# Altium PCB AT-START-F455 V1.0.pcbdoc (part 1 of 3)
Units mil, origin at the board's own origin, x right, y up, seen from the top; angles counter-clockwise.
Board outline 10945.53 x 3554 mil, 2 copper layers (Top Layer, Bottom Layer); 149 components, 197 nets, 740 pads, 768 vias.
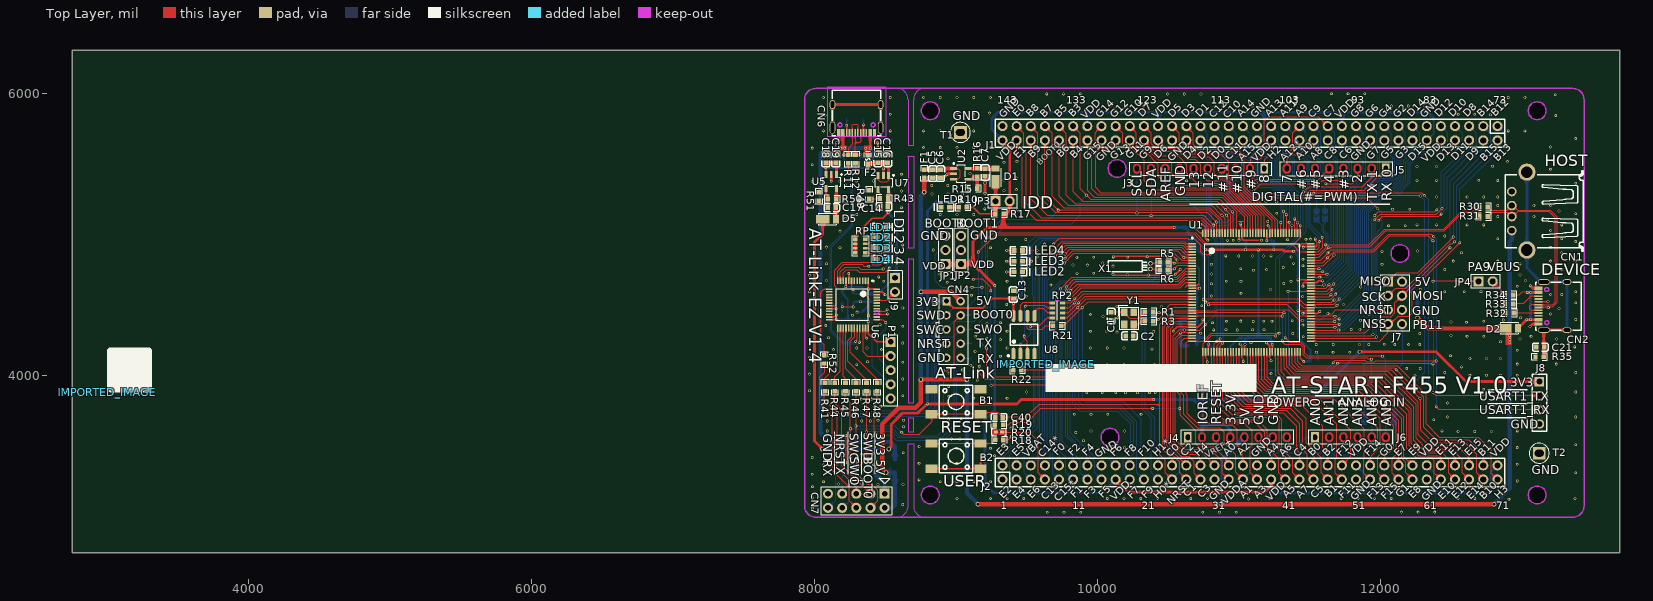
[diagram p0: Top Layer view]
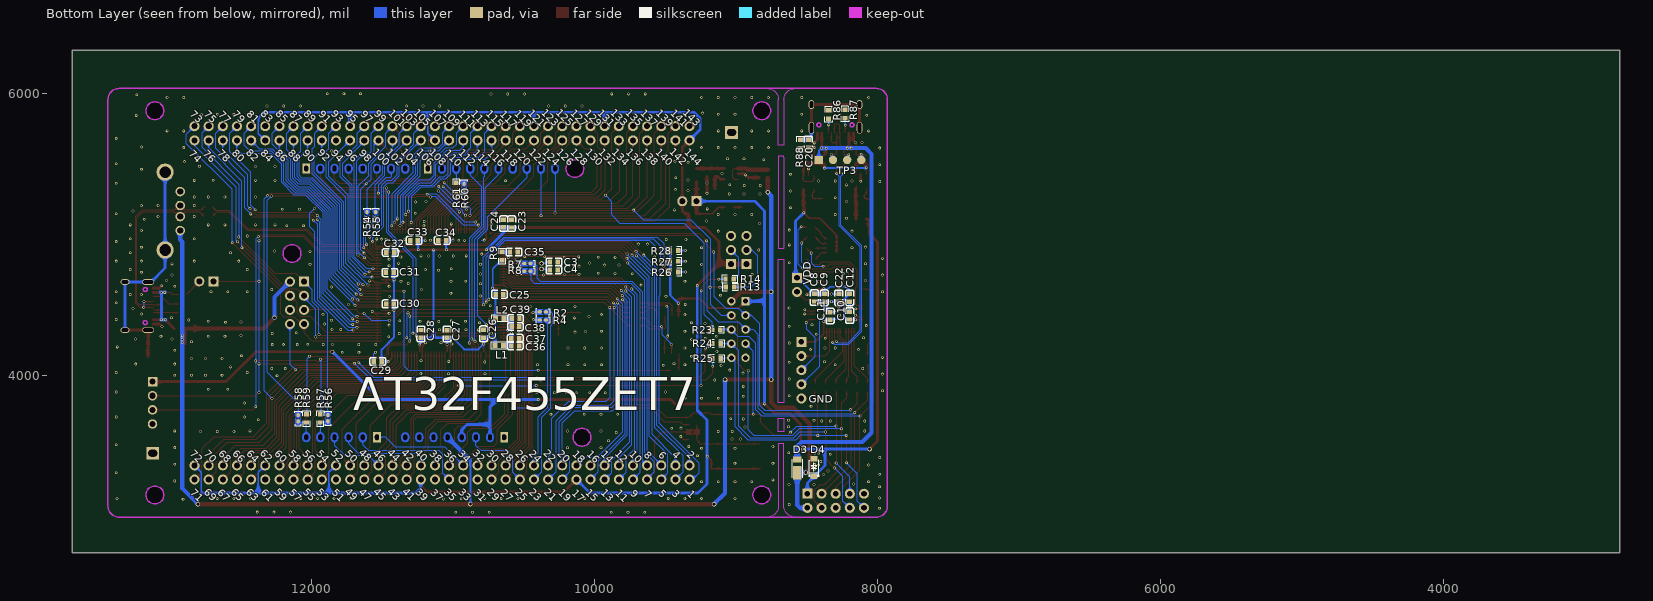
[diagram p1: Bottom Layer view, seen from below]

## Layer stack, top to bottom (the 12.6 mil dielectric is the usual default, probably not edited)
Top Layer: signal copper (thickness not stored)
Dielectric: dielectric 12.6, FR-4, Dk 4.8
Bottom Layer: signal copper (thickness not stored)

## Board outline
13695.53,2750 2750,2750 2750,6304 13695.53,6304
cut-out: 12202.8,4865.97 ccw(c12139.81,4865.43) 12076.82,4865.97 ccw(c12139.81,4866.51)
cut-out: 10202.8,5465.96 ccw(c10139.81,5465.42) 10076.82,5465.96 ccw(c10139.81,5466.5)
cut-out: 10152.8,3565.97 ccw(c10089.81,3565.43) 10026.82,3565.97 ccw(c10089.81,3566.51)
cut-out: 8881.38,5874.63 ccw(c8818.39,5874.09) 8755.4,5874.63 ccw(c8818.39,5875.17)
cut-out: 8881.38,3158.09 ccw(c8818.39,3157.55) 8755.4,3158.09 ccw(c8818.39,3158.63)
cut-out: 13172.72,3158.09 ccw(c13109.73,3157.55) 13046.74,3158.09 ccw(c13109.73,3158.63)
cut-out: 13172.72,5874.63 ccw(c13109.73,5874.09) 13046.74,5874.63 ccw(c13109.73,5875.17)

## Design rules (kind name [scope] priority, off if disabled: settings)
BoardOutlineClearance copperThickness1oz [All] p0: genericclearance=10 ignorepadtopadclearanceinfootprint=FALSE except(0: Arc-SplitContinuation Track-SplitContinuation SMDPad-SplitContinuation THPad-SplitContinuation Via-SplitContinuation Fill-SplitContinuation Poly-SplitContinuation Region-SplitContinuation Text-SplitContinuation; 6: SMDPad-CutoutEdge THPad-CutoutEdge Via-CutoutEdge Fill-CutoutEdge Region-CutoutEdge; 11.8: Track-OutlineEdge SMDPad-OutlineEdge THPad-OutlineEdge Via-OutlineEdge Fill-OutlineEdge Region-OutlineEdge Poly-OutlineEdge Text-OutlineEdge Track-CutoutEdge)
Clearance copperThickness1oz [(InNet('GND') OR InNet('PB11') OR InNet('PB9') OR InNet('PB8') OR InNet('PD4') OR InNet('PD1') OR InNet('PA1') OR InNet('PC1') OR InNet('PE15') OR InNet('PB10') OR InNet('PG6') OR InNet('PD10') OR InNet('PD9') OR InNet('PD8') OR InNet('PG15') OR InNet('PA2') OR InNet('PC0') OR InNet('PC2') OR InNet('NRST') OR InNet('PA15') OR InNet('PA13/SWDIO') OR InNet('PA14/SWCLK') OR InNet('VDD') OR InNet('PA3') OR InNet('PB2/BOOT1') OR InNet('3V3') OR InNet('PA0') OR InNet('PA5') OR InNet('PA6') OR InNet('PA7') OR InNet('PD0') OR InNet('PA9') OR InNet('PA10') OR InNet('PG14') OR InNet('PG13') OR InNet('PG11') OR InNet('PB5') OR InNet('PB6') OR InNet('PD2') OR InNet('PC12') OR InNet('PC11') OR InNet('PC10') OR InNet('VBAT') OR InNet('VDDA') OR InNet('VREF+') OR InNet('PD11') OR InNet('PD12') OR InNet('PD13') OR InNet('PD14') OR InNet('PD15') OR InNet('PG2') OR InNet('PG3') OR InNet('PG4') OR InNet('PG5') OR InNet('PG7') OR InNet('PG8') OR InNet('PC6') OR InNet('PC7') OR InNet('PC8') OR InNet('PC9') OR InNet('PA8') OR InNet('PH2') OR InNet('PH0/HEXT_IN') OR InNet('PH1/HEXT_OUT') OR InNet('PF10') OR InNet('PF9') OR InNet('PF8') OR InNet('PF7') OR InNet('PF6') OR InNet('PF5') OR InNet('PF4') OR InNet('PF3') OR InNet('PF2') OR InNet('PF1') OR InNet('PF0') OR InNet('PC13') OR InNet('PE6') OR InNet('PE5') OR InNet('PE4') OR InNet('PE3') OR InNet('PE2') OR InNet('PC15/LEXT_OUT') OR InNet('PC14/LEXT_IN') OR InNet('SWO') OR InNet('ATLK_RX') OR InNet('LD4') OR InNet('VCC') OR InNet('M-NRST') OR InNet('ATLK_TX') OR InNet('ATLINK_5V') OR InNet('PH3') OR InNet('PB3') OR InNet('QSPI1_IO2') OR InNet('QSPI1_IO1') OR InNet('PB4') OR InNet('PH1_E') OR InNet('PH0_E') OR InNet('PC15_E') OR InNet('PC14_E') OR InNet('PA11_E') OR InNet('PA12_E') OR InNet('PB0') OR InNet('PA4') OR InNet('PE10') OR InNet('PC4') OR InNet('VCC3.5V') OR InNet('PG0') OR InNet('PE7') OR InNet('PE8') OR InNet('PG1') OR InNet('LD3') OR InNet('LD2') OR InNet('LD1') OR InNet('PD3') OR InNet('PG9') OR InNet('PD6') OR InNet('M-SWDIO') OR InNet('M-ATLK_RX') OR InNet('M-ATLK_TX') OR InNet('PE1') OR InNet('PC3') OR InNet('PD7') OR InNet('PG10') OR InNet('PG12') OR InNet('M-SWCLK') OR InNet('PC5') OR InNet('PE12') OR InNet('PE11') OR InNet('PF15') OR InNet('PF14') OR InNet('PE13') OR InNet('PE14') OR InNet('PE9') OR InNet('PF12') OR InNet('PF13') OR InNet('PB1') OR InNet('PB7') OR InNet('PD5') OR InNet('PE0') OR InNet('QSPI1_SCK') OR InNet('PF11') OR InNet('QSPI1_IO0') OR InNet('QSPI1_IO3') OR InNet('$2N452') OR InNet('$2N453') OR InNet('$2N511') OR InNet('$2N512') OR InNet('$2N702') OR InNet('$2N701') OR InNet('$3N82') OR InNet('$3N81') OR InNet('$3N119') OR InNet('$3N184') OR InNet('$3N504') OR InNet('$3N505') OR InNet('$3N506') OR InNet('$4N269') OR InNet('$4N270') OR InNet('$4N339') OR InNet('$3N58') OR InNet('EGND1') OR InNet('OTGFS1_D-') OR InNet('OTGFS1_D+') OR InNet('PB12') OR InNet('PB13') OR InNet('PB14') OR InNet('PB15') OR InNet('PH4') OR InNet('QSPI1_CS') OR InNet('$3N17593') OR InNet('ATLK_SWCLK') OR InNet('$6N17598') OR InNet('ATLK_SWDIO') OR InNet('ATLK_BOOT0') OR InNet('ATLK_NRST') OR InNet('$6N17675') OR InNet('ATLK_SWO') OR InNet('PA11') OR InNet('PA12') OR InNet('$6N16959') OR InNet('EGND') OR InNet('$3N17443') OR InNet('$3N17484') OR InNet('CC2') OR InNet('USBP') OR InNet('USBM') OR InNet('CC1') OR InNet('M-BOOT0') OR InNet('$6N792') OR InNet('$6N793') OR InNet('$6N794') OR InNet('$6N795') OR InNet('M-USB_DP') OR InNet('M-USB_DM') OR InNet('5V') OR InNet('BOOT0') OR InNet('VBUS'))] p1: gap=7 ignorepadtopadclearanceinfootprint=FALSE except(6: Track-Track Track-SMDPad SMDPad-SMDPad Track-THPad SMDPad-THPad THPad-THPad Track-Via SMDPad-Via THPad-Via Via-Via Track-Fill SMDPad-Fill THPad-Fill Via-Fill Fill-Fill SMDPad-Region THPad-Region Via-Region Fill-Region Region-Region Track-Poly SMDPad-Poly THPad-Poly Via-Poly Fill-Poly Poly-Poly Track-Text SMDPad-Text THPad-Text Via-Text Fill-Text Region-Text Poly-Text Text-Text; 6.9: Track-Hole SMDPad-Hole THPad-Hole Via-Hole Fill-Hole Region-Hole Poly-Hole Text-Hole Sheet-Hole; 11.8: Track-Region Region-Poly Track-Sheet SMDPad-Sheet THPad-Sheet Via-Sheet Fill-Sheet Region-Sheet Poly-Sheet Text-Sheet)
DiffPairsRouting differentialPair [All] p1: maxuncoupledlength=10 minlimit=5.9843 maxlimit=5.9843 mostfreqgap=5.9843 toplayer_minwidth=5 toplayer_prefwidth=10 toplayer_maxwidth=100 bottomlayer_minwidth=5 bottomlayer_prefwidth=10 bottomlayer_maxwidth=100
PasteMaskExpansion pasteMaskExpansion [All] p1: expansion=0
PlaneConnect innerPlane [All] p1: planeconnectstyle=Relief reliefexpansion=20 reliefentries=4 reliefconductorwidth=10 reliefairgap=10
PolygonConnect copperRegion [All] p1: connectstyle=Relief reliefentries=4 reliefconductorwidth=10 polygonreliefangle="90 Angle" airgapwidth=10
RoutingVias viaSize [All] p1: viastyle="Through Hole" holewidth=11.811 minholewidth=11.811 maxholewidth=19.685 width=19.685 minwidth=19.685 maxwidth=31.496
SolderMaskExpansion solderMaskExpansion [All] p1: useseparateexpansions=TRUE expansion=2.0079 expansionbottom=2.0079
Width copperThickness1oz [All] p1: maxlimit=100 minlimit=6 preferedwidth=6

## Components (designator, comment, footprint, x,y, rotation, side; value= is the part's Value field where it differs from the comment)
B1 "贴片按键6*6*5 黑色" SW-SMD_4P-L6.0-W6.0-P4.50-LS9.0 9001.26,3816.97 r180 top
B2 "贴片按键6*6*5 红色" SW-SMD_4P-L6.0-W6.0-P4.50-LS9.0 9001.26,3432.97 r180 top
C1 "CL10C150JB8NNNC" C0603 10097.57,4422.61 r90 top
C2 "CL10C150JB8NNNC" C0603 10227.57,4282.61 r0 top
C3 "CL10C180JB8NNNC" C0603 10288.61,4805.53 r0 bottom
C4 "CL10C180JB8NNNC" C0603 10288.61,4749.97 r0 bottom
C5 "CL10A106KP8NNNC" C0603 8836.21,5429.61 r270 top
C6 "CC0603KRX7R9BB104" C0603 8891.21,5429.61 r270 top
C7 "CL10A106KP8NNNC" C0603 9206.21,5437.97 r270 top
C8 "CL10A475KO8NNNC" C0603 8446.37,4553.41 r90 bottom
C9 "CC0603KRX7R9BB104" C0603 8376.37,4552.61 r90 bottom
C10 "CC0603KRX7R9BB104" C0603 8196.77,4426.21 r270 bottom
C11 "CC0603KRX7R9BB104" C0603 8335.17,4423.41 r270 bottom
C12 "CC0603KRX7R9BB104" C0603 8196.37,4552.21 r90 bottom
C13 "CC0603KRX7R9BB104" C0603 9406.18,4574.85 r90 top
C14 "CL10A106KP8NNNC" C0603 8491.81,5197.16 r0 top
C15 "CL10A106KP8NNNC" C0603 8448.56,5534.05 r270 top
C16 "CC0603KRX7R9BB104" C0603 8517.56,5534.05 r270 top
C17 "CL10A106KP8NNNC" C0603 8122.56,5189.05 r0 top
C18 "CL10A106KP8NNNC" C0603 8080.37,5533.81 r270 top
C19 "CC0603KRX7R9BB104" C0603 8150.37,5533.01 r270 top
C20 "CC0603KRX7R9BB104" C0603 8489.57,5640.61 r90 bottom
C21 "CC0603KRX7R9BB104" C0603 13132.04,4203.42 r180 top
C22 "CC0603KRX7R9BB104" C0603 8273.97,4552.21 r90 bottom
C23 "CL10A475KO8NNNC" C0603 10587.57,5076.61 r90 bottom
C24 "CC0603KRX7R9BB104" C0603 10643.21,5076.97 r90 bottom
C25 "CC0603KRX7R9BB104" C0603 10673.21,4576.97 r180 bottom
C26 "CC0603KRX7R9BB104" C0603 10785.21,4297.97 r90 bottom
C27 "CC0603KRX7R9BB104" C0603 11043.21,4295.97 r90 bottom
C28 "CC0603KRX7R9BB104" C0603 11228.21,4296.97 r90 bottom
C29 "CC0603KRX7R9BB104" C0603 11534.21,4101.97 r0 bottom
C30 "CC0603KRX7R9BB104" C0603 11447.57,4508.61 r0 bottom
C31 "CC0603KRX7R9BB104" C0603 11448.57,4730.61 r0 bottom
C32 "CC0603KRX7R9BB104" C0603 11445.57,4872.61 r0 bottom
C33 "CC0603KRX7R9BB104" C0603 11277.21,4957.97 r0 bottom
C34 "CC0603KRX7R9BB104" C0603 11078.21,4958.97 r0 bottom
C35 "CC0603KRX7R9BB104" C0603 10571.21,4875.97 r180 bottom
C36 "CL10A105KB8NNNC" C0603 10561.21,4212.97 r180 bottom
C37 "CC0603KRX7R9BB104" C0603 10561.21,4264.97 r180 bottom
C38 "CC0603KRX7R9BB104" C0603 10559.57,4348.61 r180 bottom
C39 "CL10A105KB8NNNC" C0603 10559.21,4404.97 r180 bottom
C40 "CC0603KRX7R9BB104" C0603 9304.21,3705.97 r180 top
CN1 "JTJ-USB-AF-08" USB-A-TH__USB-AF-90 12984.07,5165.3 r90 top
CN2 "TYPEC-304-BCP16" USB-C-SMD_TYPEC-304-BCP16#1 13221.24,4493.82 r90 top locked
CN4 "CON10A_0" HDR2X5#1 8933.23,4527.98 r270 top
CN6 "TYPEC-304-BCP16" USB-C-SMD_TYPEC-304-BCP16#2 8297.21,5818.2 r180 top locked
CN7 "CON10" HDR2X5#2 8495.46,3166.58 r180 top
D1 "DFLS130L-7" POWERDI-123_L2.8-W1.8-LS3.7-RD 9280.21,5419.98 r90 top
D2 "DFLS130L-7" POWERDI-123_L2.8-W1.8-LS3.7-RD 12927.64,4335.82 r0 top
D3 "DFLS130L-7" POWERDI-123_L2.8-W1.8-LS3.7-RD 8567.57,3362.61 r90 bottom
D4 "SMF3.3A_C2759873" SOD-123FL_L2.8-W1.8-LS3.8-RD 8449.57,3350.61 r90 bottom
D5 "DFLS130L-7" POWERDI-123_L2.8-W1.8-LS3.7-RD 8105.61,5107.05 r0 top
F1 "SMD0603B050TF" R0603 8776.26,5429.58 r90 top
F2 "BSMD0603-050-6V" F0603 8377.56,5531.05 r270 top
IMPORTED_IMAGE "IMPORTED_IMAGE" IMPORTED_IMAGE 3000,3885.66 r0 top
IMPORTED_IMAGE "IMPORTED_IMAGE" IMPORTED_IMAGE 9636.42,4083.65 r0 top
J1 "HDR 2X36" HDR_2.54_2X36 11079.18,5715.65 r180 top locked
J2 "HDR 2X36" HDR_2.54_2X36 11079.18,3317.07 r0 top locked
J3 "CON10" "FEMALE HEADER 1X10" 10729.8,5465.97 r0 top locked
J4 "CON8" "FEMALE HEADER 1X8" 10989.8,3565.97 r0 top locked
J5 "CON8" "FEMALE HEADER 1X8" 11689.8,5465.97 r180 top locked
J6 "CON6" "FEMALE HEADER 1X6" 11789.8,3565.97 r0 top locked
J7 "Header 4X2" HDR2X4 12054.8,4666.56 r270 top locked
J8 "PZ2.54-1*4-WZ" HDR-TH_4P-P2.54-H-M-W7.7-P 13126.44,3809.71 r270 top
J9 "1X2P_2.54M" HDR1X2 8569.46,4693.58 r270 top
JP1 "Jumper 1x3P" "HEADER 1X3" 8926.21,4789.97 r90 top
JP2 "Jumper 1x3P" "HEADER 1X3" 9036.21,4789.97 r90 top
JP3 "Jumper 1x2P" "HEADER 1X2" 9280.21,5234.97 r0 top
JP4 "Jumper 1x2P" "HEADER 1X2" 12695.57,4668.61 r0 top
L1 "0.5A,600Ω@100Mhz" 0603_L 10675.26,4214.98 r180 bottom
L2 "0.5A,600Ω@100Mhz" 0603_L 10671.57,4406.61 r180 bottom
LD1 "RED" LED0603 8439.47,5052.43 r0 top
LD2 "GREEN" LED0603 8440.43,4978.33 r0 top
LD3 "BLUE" LED0603 8440.47,4901.43 r0 top
LD4 "YELLOW" LED0603 8440.43,4825.43 r0 top
LED1 "RED" LED0603 8956.21,5192.97 r180 top
LED2 "RED" LED0603 9411.05,4735 r0 top
LED3 "YELLOW" LED0603 9411.06,4809.98 r0 top
LED4 "GREEN" LED0603 9411.06,4886.28 r0 top
P1 "Header 5" HDR1X5 8538.16,4240.18 r270 top
R1 "0603WAF0000T5E" R0603 10365.57,4450.61 r0 top
R2 "NC" SB-PAD 10367.57,4452.61 r0 bottom
R3 "0603WAF0000T5E" R0603 10365.57,4386.61 r0 top
R4 "NC" SB-PAD 10367.57,4394.61 r0 bottom
R5 "0603WAF0000T5E" R0603 10469.81,4804.66 r0 top
R6 "0603WAF0000T5E" R0603 10469.81,4747.93 r0 top
R7 "NC" SB-PAD 10475.62,4794.69 r0 bottom
R8 "NC" SB-PAD 10475.62,4740.69 r0 bottom
R9 "0603WAF0000T5E" R0603 10655.21,4847.97 r270 bottom
R10 "0603WAF1001T5E" R0603 9048.26,5191.98 r180 top
R11 "0603WAF0000T5E" R0603 8238.07,5534.03 r270 top
R12 "0603WAF0000T5E" R0603 8290.08,5534.82 r270 top
R13 "0603WAF1002T5E" R0603 9044.21,4627.97 r0 bottom
R14 "0603WAF1002T5E" R0603 9045.21,4683.97 r0 bottom
R15 "0603WAF1502T5E" R0603 9122.21,5323.97 r180 top
R16 "0603WAF5102T5E" R0603 9150.21,5437.97 r90 top
R17 "0603WAF0000T5E" R0603 9308.21,5146.97 r0 top
R18 "0603WAF1003T5E" R0603 9306.21,3547.97 r180 top
R19 "0603WAF0000T5E" R0603 9305.21,3653.97 r0 top
R20 "NC" SB-PAD 9305.21,3602.97 r0 top
R21 "0603WAF330JT5E" R0603 9715.18,4353.85 r180 top
R22 "0603WAF330JT5E" R0603 9433.51,4039.99 r180 top
R23 "0603WAF4700T5E" R0603 9140.26,4325.98 r0 bottom
R24 "0603WAF4700T5E" R0603 9138.26,4229.98 r0 bottom
R25 "0603WAF4700T5E" R0603 9137.66,4123.08 r0 bottom
R26 "0603WAF1001T5E" R0603 9437.86,4735 r180 bottom
R27 "0603WAF1001T5E" R0603 9437.86,4810 r180 bottom
R28 "0603WAF1001T5E" R0603 9437.86,4886.3 r180 bottom
R30 "0603WAF0000T5E" R0603 12730.98,5194.62 r0 top
R31 "0603WAF0000T5E" R0603 12730.98,5127.69 r0 top
R32 "0603WAF5101T5E" R0603 12913.57,4444.61 r0 top
R33 "0603WAF5101T5E" R0603 12911.57,4508.61 r0 top
R34 "0603WAF1002T5E" R0603 12911.57,4572.61 r0 top
R35 "RC0603FR-071ML" R0603 13128.04,4135.42 r0 top
R41 "0603WAF330JT5E" R0603 8073.66,3920.18 r270 top
R43 "0603WAF4702T5E" R0603 8491.56,5253.41 r180 top
R44 "0603WAF330JT5E" R0603 8143.66,3920.18 r270 top
R45 "0603WAF330JT5E" R0603 8218.66,3920.18 r270 top
R46 "0603WAF330JT5E" R0603 8292.66,3920.18 r270 top
R47 "0603WAF330JT5E" R0603 8367.66,3920.18 r270 top
R48 "0603WAF330JT5E" R0603 8443.66,3920.18 r270 top
R49 "0603WAF1502T5E" R0603 8387.57,5282.61 r90 top
R50 "0603WAF5102T5E" R0603 8122.56,5251.05 r180 top
R51 "0603WAF1502T5E" R0603 8029.57,5268.61 r90 top
R52 "0603WAF330JT5E" R0603 8068.66,4117.18 r270 top
R54 "NC" SB-PAD 11609.39,5135.54 r270 bottom
R55 "NC" SB-PAD 11549.03,5134.76 r270 bottom
R56 "NC" SB-PAD 11886.21,3699.97 r270 bottom
R57 "0603WAF0000T5E" R0603 11940.21,3699.97 r270 bottom
R58 "NC" SB-PAD 12096.95,3699.18 r270 bottom
R59 "0603WAF0000T5E" R0603 12037.06,3699.96 r270 bottom
R60 "NC" SB-PAD 10923.85,5335.18 r270 bottom
R61 "0603WAF0000T5E" R0603 10979.21,5334.97 r90 bottom
R86 "0603WAF5101T5E" R0603 8345.57,5848.61 r90 bottom
R87 "0603WAF5101T5E" R0603 8229.57,5852.61 r90 bottom
R88 "RC0603FR-071ML" R0603 8543.57,5638.61 r270 bottom
RP1 "4D03WGJ0102T5E" RES-ARRAY-SMD_0603-8P-L3.2-W1.6-BL 8324.77,4918.21 r270 top
RP2 "33R" 0603*4,8P4R 9753.18,4409.85 r90 top
T1 "TESTPOINT TP-5006" TESTHOOK 9031.47,5721.74 r0 top
T2 "TESTPOINT TP-5006" TESTHOOK 13124.91,3453.21 r0 top
TP3 "1X4P_2.54F" "HDR1X4 - TOP" 8414.58,5526.61 r0 bottom
U1 "AT32F457ZET7" LQFP144_20*20 11090.17,4589.99 r0 top locked
U2 "RT9080N-08GJ5" SOT-23-5 9049.21,5365.97 r0 top
U5 "RT9080N-08GJ5" SOT-23-5 8055.56,5359.05 r270 top
U6 "AT32F403ACCT7" "LQFP48 - 2" 8380.17,4672.63 r270 top locked
U7 "RT9080N-08GJ5" SOT-23-5 8424.34,5353.39 r270 top
U8 "EN25QH128A-104HIP" SOIC-8_208MIL 9481.16,4289.78 r0 top locked
X1 "X206032768KGB2SC" OSC-TH_BD2.0-P0.70-D0.3 10374.96,4775.61 r0 top
Y1 "CJ13-080001210B20" CRYSTAL-SMD_4P-L3.2-W2.5-BL 10223.57,4406.61 r270 top

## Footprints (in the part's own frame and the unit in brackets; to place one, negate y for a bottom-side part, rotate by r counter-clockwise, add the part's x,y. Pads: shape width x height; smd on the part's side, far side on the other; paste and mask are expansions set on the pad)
0603*4,8P4R [mm]
  rect 0.55x0.95 smd: 1(0,0) 4(2.7,0) 5(2.7,1.85) 8(0,1.85)
  rect 0.5x0.95 smd: 2(0.9,0) 3(1.8,0) 6(1.8,1.85) 7(0.9,1.85)
  silkscreen extent -0.43,0.94 3.1,0.94
0603_L [mm]
  rect 0.93x0.9 smd: 1(-0.77,0) 2(0.77,0)
  silkscreen extent -1.4,-0.64 1.4,0.64
C0603 [mm]
  rect 0.8x0.9 smd: 1(-0.7,0) 2(0.7,0)
  silkscreen extent -1.41,-0.71 1.39,0.72
CRYSTAL-SMD_4P-L3.2-W2.5-BL [mm]
  rect 1.4x1.2 smd: 1(-1.1,-0.85) 2(1.1,-0.85) 3(1.1,0.85) 4(-1.1,0.85)
  silkscreen extent -2.26,-1.91 2.03,1.68
F0603 [mil]
  rect 31.75x34.02 smd: 1(-29.66,0) 2(29.66,0)
  silkscreen extent -55,-25 55,25
"FEMALE HEADER 1X6" [mm]
  rect 1.4x1.8 hole 0.7 slot 1 at 90 deg: 1(-6.35,0)
  oval 0.6x0.42 hole 0.7 slot 1 at 90 deg: 2(-3.81,0) 3(-1.27,0) 4(1.27,0) 5(3.81,0) 6(6.35,0)
  Top Layer region: 7.05,-0.2 6.956,-0.55 6.7,-0.806 6.35,-0.9 6,-0.806 5.744,-0.55 5.65,-0.2 5.65,0.2 5.744,0.55 6,0.806 6.35,0.9 6.7,0.806 6.956,0.55 7.05,0.2
  Top Layer region: 4.51,-0.2 4.416,-0.55 4.16,-0.806 3.81,-0.9 3.46,-0.806 3.204,-0.55 3.11,-0.2 3.11,0.2 3.204,0.55 3.46,0.806 3.81,0.9 4.16,0.806 4.416,0.55 4.51,0.2
  Top Layer region: 1.97,-0.2 1.876,-0.55 1.62,-0.806 1.27,-0.9 0.92,-0.806 0.664,-0.55 0.57,-0.2 0.57,0.2 0.664,0.55 0.92,0.806 1.27,0.9 1.62,0.806 1.876,0.55 1.97,0.2
  Top Layer region: -0.57,-0.2 -0.664,-0.55 -0.92,-0.806 -1.27,-0.9 -1.62,-0.806 -1.876,-0.55 -1.97,-0.2 -1.97,0.2 -1.876,0.55 -1.62,0.806 -1.27,0.9 -0.92,0.806 -0.664,0.55 -0.57,0.2
  Top Layer region: -3.11,-0.2 -3.204,-0.55 -3.46,-0.806 -3.81,-0.9 -4.16,-0.806 -4.416,-0.55 -4.51,-0.2 -4.51,0.2 -4.416,0.55 -4.16,0.806 -3.81,0.9 -3.46,0.806 -3.204,0.55 -3.11,0.2
  Bottom Layer region: 7.05,-0.2 6.956,-0.55 6.7,-0.806 6.35,-0.9 6,-0.806 5.744,-0.55 5.65,-0.2 5.65,0.2 5.744,0.55 6,0.806 6.35,0.9 6.7,0.806 6.956,0.55 7.05,0.2
  Bottom Layer region: 4.51,-0.2 4.416,-0.55 4.16,-0.806 3.81,-0.9 3.46,-0.806 3.204,-0.55 3.11,-0.2 3.11,0.2 3.204,0.55 3.46,0.806 3.81,0.9 4.16,0.806 4.416,0.55 4.51,0.2
  Bottom Layer region: 1.97,-0.2 1.876,-0.55 1.62,-0.806 1.27,-0.9 0.92,-0.806 0.664,-0.55 0.57,-0.2 0.57,0.2 0.664,0.55 0.92,0.806 1.27,0.9 1.62,0.806 1.876,0.55 1.97,0.2
  Bottom Layer region: -0.57,-0.2 -0.664,-0.55 -0.92,-0.806 -1.27,-0.9 -1.62,-0.806 -1.876,-0.55 -1.97,-0.2 -1.97,0.2 -1.876,0.55 -1.62,0.806 -1.27,0.9 -0.92,0.806 -0.664,0.55 -0.57,0.2
  Bottom Layer region: -3.11,-0.2 -3.204,-0.55 -3.46,-0.806 -3.81,-0.9 -4.16,-0.806 -4.416,-0.55 -4.51,-0.2 -4.51,0.2 -4.416,0.55 -4.16,0.806 -3.81,0.9 -3.46,0.806 -3.204,0.55 -3.11,0.2
  Multi-Layer region: 7.05,-0.2 6.956,-0.55 6.7,-0.806 6.35,-0.9 6,-0.806 5.744,-0.55 5.65,-0.2 5.65,0.2 5.744,0.55 6,0.806 6.35,0.9 6.7,0.806 6.956,0.55 7.05,0.2
  Multi-Layer region: 4.51,-0.2 4.416,-0.55 4.16,-0.806 3.81,-0.9 3.46,-0.806 3.204,-0.55 3.11,-0.2 3.11,0.2 3.204,0.55 3.46,0.806 3.81,0.9 4.16,0.806 4.416,0.55 4.51,0.2
  Multi-Layer region: 1.97,-0.2 1.876,-0.55 1.62,-0.806 1.27,-0.9 0.92,-0.806 0.664,-0.55 0.57,-0.2 0.57,0.2 0.664,0.55 0.92,0.806 1.27,0.9 1.62,0.806 1.876,0.55 1.97,0.2
  Multi-Layer region: -0.57,-0.2 -0.664,-0.55 -0.92,-0.806 -1.27,-0.9 -1.62,-0.806 -1.876,-0.55 -1.97,-0.2 -1.97,0.2 -1.876,0.55 -1.62,0.806 -1.27,0.9 -0.92,0.806 -0.664,0.55 -0.57,0.2
  Multi-Layer region: -3.11,-0.2 -3.204,-0.55 -3.46,-0.806 -3.81,-0.9 -4.16,-0.806 -4.416,-0.55 -4.51,-0.2 -4.51,0.2 -4.416,0.55 -4.16,0.806 -3.81,0.9 -3.46,0.806 -3.204,0.55 -3.11,0.2
  silkscreen extent -7.62,-1.17 7.62,1.27
"FEMALE HEADER 1X8" [mm]
  rect 1.4x1.8 hole 0.7 slot 1 at 90 deg: 1(-8.89,0)
  oval 0.6x0.42 hole 0.7 slot 1 at 90 deg: 2(-6.35,0) 3(-3.81,0) 4(-1.27,0) 5(1.27,0) 6(3.81,0) 7(6.35,0) 8(8.89,0)
  Top Layer region: 9.59,-0.2 9.496,-0.55 9.24,-0.806 8.89,-0.9 8.54,-0.806 8.284,-0.55 8.19,-0.2 8.19,0.2 8.284,0.55 8.54,0.806 8.89,0.9 9.24,0.806 9.496,0.55 9.59,0.2
  Top Layer region: 7.05,-0.2 6.956,-0.55 6.7,-0.806 6.35,-0.9 6,-0.806 5.744,-0.55 5.65,-0.2 5.65,0.2 5.744,0.55 6,0.806 6.35,0.9 6.7,0.806 6.956,0.55 7.05,0.2
  Top Layer region: 4.51,-0.2 4.416,-0.55 4.16,-0.806 3.81,-0.9 3.46,-0.806 3.204,-0.55 3.11,-0.2 3.11,0.2 3.204,0.55 3.46,0.806 3.81,0.9 4.16,0.806 4.416,0.55 4.51,0.2
  Top Layer region: 1.97,-0.2 1.876,-0.55 1.62,-0.806 1.27,-0.9 0.92,-0.806 0.664,-0.55 0.57,-0.2 0.57,0.2 0.664,0.55 0.92,0.806 1.27,0.9 1.62,0.806 1.876,0.55 1.97,0.2
  Top Layer region: -0.57,-0.2 -0.664,-0.55 -0.92,-0.806 -1.27,-0.9 -1.62,-0.806 -1.876,-0.55 -1.97,-0.2 -1.97,0.2 -1.876,0.55 -1.62,0.806 -1.27,0.9 -0.92,0.806 -0.664,0.55 -0.57,0.2
  Top Layer region: -3.11,-0.2 -3.204,-0.55 -3.46,-0.806 -3.81,-0.9 -4.16,-0.806 -4.416,-0.55 -4.51,-0.2 -4.51,0.2 -4.416,0.55 -4.16,0.806 -3.81,0.9 -3.46,0.806 -3.204,0.55 -3.11,0.2
  Top Layer region: -5.65,-0.2 -5.744,-0.55 -6,-0.806 -6.35,-0.9 -6.7,-0.806 -6.956,-0.55 -7.05,-0.2 -7.05,0.2 -6.956,0.55 -6.7,0.806 -6.35,0.9 -6,0.806 -5.744,0.55 -5.65,0.2
  Bottom Layer region: 9.59,-0.2 9.496,-0.55 9.24,-0.806 8.89,-0.9 8.54,-0.806 8.284,-0.55 8.19,-0.2 8.19,0.2 8.284,0.55 8.54,0.806 8.89,0.9 9.24,0.806 9.496,0.55 9.59,0.2
  Bottom Layer region: 7.05,-0.2 6.956,-0.55 6.7,-0.806 6.35,-0.9 6,-0.806 5.744,-0.55 5.65,-0.2 5.65,0.2 5.744,0.55 6,0.806 6.35,0.9 6.7,0.806 6.956,0.55 7.05,0.2
  Bottom Layer region: 4.51,-0.2 4.416,-0.55 4.16,-0.806 3.81,-0.9 3.46,-0.806 3.204,-0.55 3.11,-0.2 3.11,0.2 3.204,0.55 3.46,0.806 3.81,0.9 4.16,0.806 4.416,0.55 4.51,0.2
  Bottom Layer region: 1.97,-0.2 1.876,-0.55 1.62,-0.806 1.27,-0.9 0.92,-0.806 0.664,-0.55 0.57,-0.2 0.57,0.2 0.664,0.55 0.92,0.806 1.27,0.9 1.62,0.806 1.876,0.55 1.97,0.2
  Bottom Layer region: -0.57,-0.2 -0.664,-0.55 -0.92,-0.806 -1.27,-0.9 -1.62,-0.806 -1.876,-0.55 -1.97,-0.2 -1.97,0.2 -1.876,0.55 -1.62,0.806 -1.27,0.9 -0.92,0.806 -0.664,0.55 -0.57,0.2
  Bottom Layer region: -3.11,-0.2 -3.204,-0.55 -3.46,-0.806 -3.81,-0.9 -4.16,-0.806 -4.416,-0.55 -4.51,-0.2 -4.51,0.2 -4.416,0.55 -4.16,0.806 -3.81,0.9 -3.46,0.806 -3.204,0.55 -3.11,0.2
  Bottom Layer region: -5.65,-0.2 -5.744,-0.55 -6,-0.806 -6.35,-0.9 -6.7,-0.806 -6.956,-0.55 -7.05,-0.2 -7.05,0.2 -6.956,0.55 -6.7,0.806 -6.35,0.9 -6,0.806 -5.744,0.55 -5.65,0.2
  Multi-Layer region: 9.59,-0.2 9.496,-0.55 9.24,-0.806 8.89,-0.9 8.54,-0.806 8.284,-0.55 8.19,-0.2 8.19,0.2 8.284,0.55 8.54,0.806 8.89,0.9 9.24,0.806 9.496,0.55 9.59,0.2
  Multi-Layer region: 7.05,-0.2 6.956,-0.55 6.7,-0.806 6.35,-0.9 6,-0.806 5.744,-0.55 5.65,-0.2 5.65,0.2 5.744,0.55 6,0.806 6.35,0.9 6.7,0.806 6.956,0.55 7.05,0.2
  Multi-Layer region: 4.51,-0.2 4.416,-0.55 4.16,-0.806 3.81,-0.9 3.46,-0.806 3.204,-0.55 3.11,-0.2 3.11,0.2 3.204,0.55 3.46,0.806 3.81,0.9 4.16,0.806 4.416,0.55 4.51,0.2
  Multi-Layer region: 1.97,-0.2 1.876,-0.55 1.62,-0.806 1.27,-0.9 0.92,-0.806 0.664,-0.55 0.57,-0.2 0.57,0.2 0.664,0.55 0.92,0.806 1.27,0.9 1.62,0.806 1.876,0.55 1.97,0.2
  Multi-Layer region: -0.57,-0.2 -0.664,-0.55 -0.92,-0.806 -1.27,-0.9 -1.62,-0.806 -1.876,-0.55 -1.97,-0.2 -1.97,0.2 -1.876,0.55 -1.62,0.806 -1.27,0.9 -0.92,0.806 -0.664,0.55 -0.57,0.2
  Multi-Layer region: -3.11,-0.2 -3.204,-0.55 -3.46,-0.806 -3.81,-0.9 -4.16,-0.806 -4.416,-0.55 -4.51,-0.2 -4.51,0.2 -4.416,0.55 -4.16,0.806 -3.81,0.9 -3.46,0.806 -3.204,0.55 -3.11,0.2
  Multi-Layer region: -5.65,-0.2 -5.744,-0.55 -6,-0.806 -6.35,-0.9 -6.7,-0.806 -6.956,-0.55 -7.05,-0.2 -7.05,0.2 -6.956,0.55 -6.7,0.806 -6.35,0.9 -6,0.806 -5.744,0.55 -5.65,0.2
  silkscreen extent -10.16,-1.17 10.16,1.27
"FEMALE HEADER 1X10" [mm]
  rect 1.4x1.8 hole 0.7 slot 1 at 90 deg: 1(11.43,0)
  oval 0.6x0.42 hole 0.7 slot 1 at 90 deg: 2(8.89,0) 3(6.35,0) 4(3.81,0) 5(1.27,0) 6(-1.27,0) 7(-3.81,0) 8(-6.35,0) 9(-8.89,0) 10(-11.43,0)
  Top Layer region: -12.13,0.2 -12.036,0.55 -11.78,0.806 -11.43,0.9 -11.08,0.806 -10.824,0.55 -10.73,0.2 -10.73,-0.2 -10.824,-0.55 -11.08,-0.806 -11.43,-0.9 -11.78,-0.806 -12.036,-0.55 -12.13,-0.2
  Top Layer region: -9.59,0.2 -9.496,0.55 -9.24,0.806 -8.89,0.9 -8.54,0.806 -8.284,0.55 -8.19,0.2 -8.19,-0.2 -8.284,-0.55 -8.54,-0.806 -8.89,-0.9 -9.24,-0.806 -9.496,-0.55 -9.59,-0.2
  Top Layer region: -7.05,0.2 -6.956,0.55 -6.7,0.806 -6.35,0.9 -6,0.806 -5.744,0.55 -5.65,0.2 -5.65,-0.2 -5.744,-0.55 -6,-0.806 -6.35,-0.9 -6.7,-0.806 -6.956,-0.55 -7.05,-0.2
  Top Layer region: -4.51,0.2 -4.416,0.55 -4.16,0.806 -3.81,0.9 -3.46,0.806 -3.204,0.55 -3.11,0.2 -3.11,-0.2 -3.204,-0.55 -3.46,-0.806 -3.81,-0.9 -4.16,-0.806 -4.416,-0.55 -4.51,-0.2
  Top Layer region: -1.97,0.2 -1.876,0.55 -1.62,0.806 -1.27,0.9 -0.92,0.806 -0.664,0.55 -0.57,0.2 -0.57,-0.2 -0.664,-0.55 -0.92,-0.806 -1.27,-0.9 -1.62,-0.806 -1.876,-0.55 -1.97,-0.2
  Top Layer region: 0.57,0.2 0.664,0.55 0.92,0.806 1.27,0.9 1.62,0.806 1.876,0.55 1.97,0.2 1.97,-0.2 1.876,-0.55 1.62,-0.806 1.27,-0.9 0.92,-0.806 0.664,-0.55 0.57,-0.2
  Top Layer region: 3.11,0.2 3.204,0.55 3.46,0.806 3.81,0.9 4.16,0.806 4.416,0.55 4.51,0.2 4.51,-0.2 4.416,-0.55 4.16,-0.806 3.81,-0.9 3.46,-0.806 3.204,-0.55 3.11,-0.2
  Top Layer region: 5.65,0.2 5.744,0.55 6,0.806 6.35,0.9 6.7,0.806 6.956,0.55 7.05,0.2 7.05,-0.2 6.956,-0.55 6.7,-0.806 6.35,-0.9 6,-0.806 5.744,-0.55 5.65,-0.2
  Top Layer region: 8.19,0.2 8.284,0.55 8.54,0.806 8.89,0.9 9.24,0.806 9.496,0.55 9.59,0.2 9.59,-0.2 9.496,-0.55 9.24,-0.806 8.89,-0.9 8.54,-0.806 8.284,-0.55 8.19,-0.2
  Bottom Layer region: -12.13,0.2 -12.036,0.55 -11.78,0.806 -11.43,0.9 -11.08,0.806 -10.824,0.55 -10.73,0.2 -10.73,-0.2 -10.824,-0.55 -11.08,-0.806 -11.43,-0.9 -11.78,-0.806 -12.036,-0.55 -12.13,-0.2
  Bottom Layer region: -9.59,0.2 -9.496,0.55 -9.24,0.806 -8.89,0.9 -8.54,0.806 -8.284,0.55 -8.19,0.2 -8.19,-0.2 -8.284,-0.55 -8.54,-0.806 -8.89,-0.9 -9.24,-0.806 -9.496,-0.55 -9.59,-0.2
  Bottom Layer region: -7.05,0.2 -6.956,0.55 -6.7,0.806 -6.35,0.9 -6,0.806 -5.744,0.55 -5.65,0.2 -5.65,-0.2 -5.744,-0.55 -6,-0.806 -6.35,-0.9 -6.7,-0.806 -6.956,-0.55 -7.05,-0.2
  Bottom Layer region: -4.51,0.2 -4.416,0.55 -4.16,0.806 -3.81,0.9 -3.46,0.806 -3.204,0.55 -3.11,0.2 -3.11,-0.2 -3.204,-0.55 -3.46,-0.806 -3.81,-0.9 -4.16,-0.806 -4.416,-0.55 -4.51,-0.2
  Bottom Layer region: -1.97,0.2 -1.876,0.55 -1.62,0.806 -1.27,0.9 -0.92,0.806 -0.664,0.55 -0.57,0.2 -0.57,-0.2 -0.664,-0.55 -0.92,-0.806 -1.27,-0.9 -1.62,-0.806 -1.876,-0.55 -1.97,-0.2
  Bottom Layer region: 0.57,0.2 0.664,0.55 0.92,0.806 1.27,0.9 1.62,0.806 1.876,0.55 1.97,0.2 1.97,-0.2 1.876,-0.55 1.62,-0.806 1.27,-0.9 0.92,-0.806 0.664,-0.55 0.57,-0.2
  Bottom Layer region: 3.11,0.2 3.204,0.55 3.46,0.806 3.81,0.9 4.16,0.806 4.416,0.55 4.51,0.2 4.51,-0.2 4.416,-0.55 4.16,-0.806 3.81,-0.9 3.46,-0.806 3.204,-0.55 3.11,-0.2
  Bottom Layer region: 5.65,0.2 5.744,0.55 6,0.806 6.35,0.9 6.7,0.806 6.956,0.55 7.05,0.2 7.05,-0.2 6.956,-0.55 6.7,-0.806 6.35,-0.9 6,-0.806 5.744,-0.55 5.65,-0.2
  Bottom Layer region: 8.19,0.2 8.284,0.55 8.54,0.806 8.89,0.9 9.24,0.806 9.496,0.55 9.59,0.2 9.59,-0.2 9.496,-0.55 9.24,-0.806 8.89,-0.9 8.54,-0.806 8.284,-0.55 8.19,-0.2
  Multi-Layer region: -12.13,0.2 -12.036,0.55 -11.78,0.806 -11.43,0.9 -11.08,0.806 -10.824,0.55 -10.73,0.2 -10.73,-0.2 -10.824,-0.55 -11.08,-0.806 -11.43,-0.9 -11.78,-0.806 -12.036,-0.55 -12.13,-0.2
  Multi-Layer region: -9.59,0.2 -9.496,0.55 -9.24,0.806 -8.89,0.9 -8.54,0.806 -8.284,0.55 -8.19,0.2 -8.19,-0.2 -8.284,-0.55 -8.54,-0.806 -8.89,-0.9 -9.24,-0.806 -9.496,-0.55 -9.59,-0.2
  Multi-Layer region: -7.05,0.2 -6.956,0.55 -6.7,0.806 -6.35,0.9 -6,0.806 -5.744,0.55 -5.65,0.2 -5.65,-0.2 -5.744,-0.55 -6,-0.806 -6.35,-0.9 -6.7,-0.806 -6.956,-0.55 -7.05,-0.2
  Multi-Layer region: -4.51,0.2 -4.416,0.55 -4.16,0.806 -3.81,0.9 -3.46,0.806 -3.204,0.55 -3.11,0.2 -3.11,-0.2 -3.204,-0.55 -3.46,-0.806 -3.81,-0.9 -4.16,-0.806 -4.416,-0.55 -4.51,-0.2
  Multi-Layer region: -1.97,0.2 -1.876,0.55 -1.62,0.806 -1.27,0.9 -0.92,0.806 -0.664,0.55 -0.57,0.2 -0.57,-0.2 -0.664,-0.55 -0.92,-0.806 -1.27,-0.9 -1.62,-0.806 -1.876,-0.55 -1.97,-0.2
  Multi-Layer region: 0.57,0.2 0.664,0.55 0.92,0.806 1.27,0.9 1.62,0.806 1.876,0.55 1.97,0.2 1.97,-0.2 1.876,-0.55 1.62,-0.806 1.27,-0.9 0.92,-0.806 0.664,-0.55 0.57,-0.2
  Multi-Layer region: 3.11,0.2 3.204,0.55 3.46,0.806 3.81,0.9 4.16,0.806 4.416,0.55 4.51,0.2 4.51,-0.2 4.416,-0.55 4.16,-0.806 3.81,-0.9 3.46,-0.806 3.204,-0.55 3.11,-0.2
  Multi-Layer region: 5.65,0.2 5.744,0.55 6,0.806 6.35,0.9 6.7,0.806 6.956,0.55 7.05,0.2 7.05,-0.2 6.956,-0.55 6.7,-0.806 6.35,-0.9 6,-0.806 5.744,-0.55 5.65,-0.2
  Multi-Layer region: 8.19,0.2 8.284,0.55 8.54,0.806 8.89,0.9 9.24,0.806 9.496,0.55 9.59,0.2 9.59,-0.2 9.496,-0.55 9.24,-0.806 8.89,-0.9 8.54,-0.806 8.284,-0.55 8.19,-0.2
  silkscreen extent -12.67,-1.27 12.7,1.17
HDR1X2 [mm]
  rect 1.8x1.8 hole 1: 1(0,0)
  round 1.8 hole 1: 2(2.54,0)
  silkscreen extent -1.27,-1.27 3.81,1.27
"HDR1X4 - TOP" [mm]
  rect 1.5x1.5 smd: 1(0,0)
  round 1.5 smd: 2(-2.54,0) 3(-5.08,0) 4(-7.62,0)
HDR1X5 [mm]
  rect 1.8x1.8 hole 1: 1(0,0)
  round 1.8 hole 1: 2(2.54,0) 3(5.08,0) 4(7.62,0) 5(10.16,0)
  silkscreen extent -1.27,-1.27 11.43,1.27
HDR2X4 [mm]
  rect 1.8x1.8 hole 1 slot 1.005 at 0 deg: 1(0,0)
  round 1.8 hole 1 slot 1.005 at 0 deg: 2(0,2.54) 3(2.54,0) 4(2.54,2.54) 5(5.08,0) 6(5.08,2.54) 7(7.62,0) 8(7.62,2.54)
  silkscreen extent -1.27,-1.27 8.89,3.81
HDR2X5#1 [mm]
  rect 1.5x1.5 hole 0.9: 1(0,0)
  round 1.5 hole 0.9: 2(0,2.54) 3(2.54,0) 4(2.54,2.54) 5(5.08,0) 6(5.08,2.54) 7(7.62,0) 8(7.62,2.54) 9(10.16,0) 10(10.16,2.54)
  silkscreen extent -1.27,-1.27 11.43,3.81
HDR2X5#2 [mm]
  rect 1.8x1.8 hole 1: 1(0,0)
  round 1.8 hole 1: 2(0,2.54) 3(2.54,0) 4(2.54,2.54) 5(5.08,0) 6(5.08,2.54) 7(7.62,0) 8(7.62,2.54) 9(10.16,0) 10(10.16,2.54)
  silkscreen extent -1.27,-1.27 11.43,3.81
HDR-TH_4P-P2.54-H-M-W7.7-P [mm]
  rect 1.7x1.7 hole 1.1: 1(-3.81,0)
  round 1.7 hole 1.1: 2(-1.27,0) 3(1.27,0) 4(3.81,0)
  silkscreen extent -5.09,-1.27 5.09,1.27
HDR_2.54_2X36 [mm]
  round 1.8 hole 1.1: 1(-44.45,-1.27) 2(-44.45,1.27) 3(-41.91,-1.27) 4(-41.91,1.27) 5(-39.37,-1.27) 6(-39.37,1.27) 7(-36.83,-1.27) 8(-36.83,1.27) 9(-34.29,-1.27) 10(-34.29,1.27) 11(-31.75,-1.27) 12(-31.75,1.27) 13(-29.21,-1.27) 14(-29.21,1.27) 15(-26.67,-1.27) 16(-26.67,1.27) 17(-24.13,-1.27) 18(-24.13,1.27) 19(-21.59,-1.27) 20(-21.59,1.27) 21(-19.05,-1.27) 22(-19.05,1.27) 23(-16.51,-1.27) 24(-16.51,1.27) 25(-13.97,-1.27) 26(-13.97,1.27) 27(-11.43,-1.27) 28(-11.43,1.27) 29(-8.89,-1.27) 30(-8.89,1.27) 31(-6.35,-1.27) 32(-6.35,1.27) 33(-3.81,-1.27) 34(-3.81,1.27) 35(-1.27,-1.27) 36(-1.27,1.27) 37(1.27,-1.27) 38(1.27,1.27) 39(3.81,-1.27) 40(3.81,1.27) 41(6.35,-1.27) 42(6.35,1.27) 43(8.89,-1.27) 44(8.89,1.27) 45(11.43,-1.27) 46(11.43,1.27) 47(13.97,-1.27) 48(13.97,1.27) 49(16.51,-1.27) 50(16.51,1.27) 51(19.05,-1.27) 52(19.05,1.27) 53(21.59,-1.27) 54(21.59,1.27) 55(24.13,-1.27) 56(24.13,1.27) 57(26.67,-1.27) 58(26.67,1.27) 59(29.21,-1.27) 60(29.21,1.27) 61(31.75,-1.27) 62(31.75,1.27) 63(34.29,-1.27) 64(34.29,1.27) 65(36.83,-1.27) 66(36.83,1.27) 67(39.37,-1.27) 68(39.37,1.27) 69(41.91,-1.27) 70(41.91,1.27) 71(44.45,-1.27) 72(44.45,1.27)
  silkscreen extent -45.72,-2.54 45.72,2.54
"HEADER 1X2" [mm]
  rect 1.8x1.8 hole 1 slot 1.005 at 0 deg: 1(0,0)
  round 1.8 hole 1 slot 1.005 at 0 deg: 2(2.54,0)
  silkscreen extent -1.27,-1.27 3.81,1.27
"HEADER 1X3" [mm]
  rect 1.8x1.8 hole 1 slot 1.005 at 0 deg: 1(0,0)
  round 1.8 hole 1 slot 1.005 at 0 deg copper offset 0,0: 2(2.54,0) 3(5.08,0)
  silkscreen extent -1.27,-1.27 6.35,1.27
IMPORTED_IMAGE [mil]
  silkscreen extent 0,0 315,315
LED0603 [mil]
  rect 36x32 smd: 1(-0.04,0.2) 2(60.96,0.2)
  silkscreen extent -28,-28 110,27
"LQFP48 - 2" [mm]
  rect 1.2x0.3 smd: 1(0,0) 2(0,-0.5) 3(0,-1) 4(0,-1.5) 5(0,-2) 6(0,-2.5) 7(0,-3) 8(0,-3.5) 9(0,-4) 10(0,-4.5) 11(0,-5) 12(0,-5.5) 25(8.5,-5.5) 26(8.5,-5) 27(8.5,-4.5) 28(8.5,-4) 29(8.5,-3.5) 30(8.5,-3) 31(8.5,-2.5) 32(8.5,-2) 33(8.5,-1.5) 34(8.5,-1) 35(8.5,-0.5) 36(8.5,0)
  rect 0.3x1.2 smd: 13(1.5,-7) 14(2,-7) 15(2.5,-7) 16(3,-7) 17(3.5,-7) 18(4,-7) 19(4.5,-7) 20(5,-7) 21(5.5,-7) 22(6,-7) 23(6.5,-7) 24(7,-7) 37(7,1.5) 38(6.5,1.5) 39(6,1.5) 40(5.5,1.5) 41(5,1.5) 42(4.5,1.5) 43(4,1.5) 44(3.5,1.5) 45(3,1.5) 46(2.5,1.5) 47(2,1.5) 48(1.5,1.5)
  silkscreen extent -0.12,-5.71 7.11,0.89
LQFP144_20*20 [mm]
  rect 1.35x0.3 smd: 1(-10.625,8.75) 2(-10.625,8.25) 3(-10.625,7.75) 4(-10.625,7.25) 5(-10.625,6.75) 6(-10.625,6.25) 7(-10.625,5.75) 8(-10.625,5.25) 9(-10.625,4.75) 10(-10.625,4.25) 11(-10.625,3.75) 12(-10.625,3.25) 13(-10.625,2.75) 14(-10.625,2.25) 15(-10.625,1.75) 16(-10.625,1.25) 17(-10.625,0.75) 18(-10.625,0.25) 19(-10.625,-0.25) 20(-10.625,-0.75) 21(-10.625,-1.25) 22(-10.625,-1.75) 23(-10.625,-2.25) 24(-10.625,-2.75) 25(-10.625,-3.25) 26(-10.625,-3.75) 27(-10.625,-4.25) 28(-10.625,-4.75) 29(-10.625,-5.25) 30(-10.625,-5.75) 31(-10.625,-6.25) 32(-10.625,-6.75) 33(-10.625,-7.25) 34(-10.625,-7.75) 35(-10.625,-8.25) 36(-10.625,-8.75) 73(10.625,-8.75) 74(10.625,-8.25) 75(10.625,-7.75) 76(10.625,-7.25) 77(10.625,-6.75) 78(10.625,-6.25) 79(10.625,-5.75) 80(10.625,-5.25) 81(10.625,-4.75) 82(10.625,-4.25) 83(10.625,-3.75) 84(10.625,-3.25) 85(10.625,-2.75) 86(10.625,-2.25) 87(10.625,-1.75) 88(10.625,-1.25) 89(10.625,-0.75) 90(10.625,-0.25) 91(10.625,0.25) 92(10.625,0.75) 93(10.625,1.25) 94(10.625,1.75) 95(10.625,2.25) 96(10.625,2.75) 97(10.625,3.25) 98(10.625,3.75) 99(10.625,4.25) 100(10.625,4.75) 101(10.625,5.25) 102(10.625,5.75) 103(10.625,6.25) 104(10.625,6.75) 105(10.625,7.25) 106(10.625,7.75) 107(10.625,8.25) 108(10.625,8.75)
  rect 0.3x1.35 smd: 37(-8.75,-10.625) 38(-8.25,-10.625) 39(-7.75,-10.625) 40(-7.25,-10.625) 41(-6.75,-10.625) 42(-6.25,-10.625) 43(-5.75,-10.625) 44(-5.25,-10.625) 45(-4.75,-10.625) 46(-4.25,-10.625) 47(-3.75,-10.625) 48(-3.25,-10.625) 49(-2.75,-10.625) 50(-2.25,-10.625) 51(-1.75,-10.625) 52(-1.25,-10.625) 53(-0.75,-10.625) 54(-0.25,-10.625) 55(0.25,-10.625) 56(0.75,-10.625) 57(1.25,-10.625) 58(1.75,-10.625) 59(2.25,-10.625) 60(2.75,-10.625) 61(3.25,-10.625) 62(3.75,-10.625) 63(4.25,-10.625) 64(4.75,-10.625) 65(5.25,-10.625) 66(5.75,-10.625) 67(6.25,-10.625) 68(6.75,-10.625) 69(7.25,-10.625) 70(7.75,-10.625) 71(8.25,-10.625) 72(8.75,-10.625) 109(8.75,10.625) 110(8.25,10.625) 111(7.75,10.625) 112(7.25,10.625) 113(6.75,10.625) 114(6.25,10.625) 115(5.75,10.625) 116(5.25,10.625) 117(4.75,10.625) 118(4.25,10.625) 119(3.75,10.625) 120(3.25,10.625) 121(2.75,10.625) 122(2.25,10.625) 123(1.75,10.625) 124(1.25,10.625) 125(0.75,10.625) 126(0.25,10.625) 127(-0.25,10.625) 128(-0.75,10.625) 129(-1.25,10.625) 130(-1.75,10.625) 131(-2.25,10.625) 132(-2.75,10.625) 133(-3.25,10.625) 134(-3.75,10.625) 135(-4.25,10.625) 136(-4.75,10.625) 137(-5.25,10.625) 138(-5.75,10.625) 139(-6.25,10.625) 140(-6.75,10.625) 141(-7.25,10.625) 142(-7.75,10.625) 143(-8.25,10.625) 144(-8.75,10.625)
  silkscreen extent -10.75,-8.78 8.68,9.89
OSC-TH_BD2.0-P0.70-D0.3 [mm]
  round 0.8 hole 0.5: 1(0,0.5) 2(0,-0.5)
  silkscreen extent -7.6,-1 -0.54,1
POWERDI-123_L2.8-W1.8-LS3.7-RD [mm]
  rect 2.4x1.5 smd: 1(-1.187,0)
  rect 1.05x1.5 smd: 2(1.187,0)
  silkscreen extent -2,-1 1.2,1
R0603 [mil]
  rect 31.75x34.02 smd: 1(-29.66,0) 2(29.66,0)
  silkscreen extent -55,-26 55,26
RES-ARRAY-SMD_0603-8P-L3.2-W1.6-BL [mm]
  rect 0.65x0.8 smd: 1(-1.2,-0.9) 4(1.2,-0.9) 5(1.2,0.9) 8(-1.2,0.9)
  rect 0.5x0.8 smd: 2(-0.4,-0.9) 3(0.4,-0.9) 6(0.4,0.9) 7(-0.4,0.9)
  silkscreen extent -1.87,-1.45 1.87,1.47
SB-PAD [mm]
  oval 0.735x0.6 smd: 1(-0.587,0)
  oval 0.791x0.6 smd: 2(0.541,0)
  Top Layer region: -1.2,-0.5 -1.2,0.5 -0.418,0.5 0.025,0 -0.433,-0.5
  Top Layer region: -0.119,0.5 0.381,0 -0.119,-0.5 1.2,-0.5 1.2,0.5
  silkscreen extent -1.28,-0.58 1.28,0.58
SOD-123FL_L2.8-W1.8-LS3.8-RD [mm]
  rect 0.93x1.2 smd: 1(-1.6,0) 2(1.6,0)
  silkscreen extent -1.6,-0.95 1.38,0.95
SOIC-8_208MIL [mm]
  oval 0.7x2.2 smd: 1(-1.905,-3.4) 2(-0.635,-3.4) 3(0.635,-3.4) 4(1.905,-3.4) 5(1.905,3.4) 6(0.635,3.4) 7(-0.635,3.4) 8(-1.905,3.4)
  silkscreen extent -2.95,-3.9 2.5,1.9
SOT-23-5 [mil]
  rect 50x20 smd: 1(-65,100) 2(-65,63) 3(-65,25) 4(35,25) 5(35,100)
  silkscreen extent -65,1 18,135
SW-SMD_4P-L6.0-W6.0-P4.50-LS9.0 [mm]
  rect 2.2x1.5 smd: 1(-4.4,2.25) 2(-4.4,-2.25) 3(4.4,2.25) 4(4.4,-2.25)
  silkscreen extent -3,-3 3,3
TESTHOOK [mm]
  rect 2.3x2.3 hole 1.2 slot 1.6 at 0 deg: 1(0,0)
  silkscreen extent -1.8,-1.8 1.8,1.8
USB-A-TH__USB-AF-90 [mm]
  round 1.7 hole 1.1 copper offset 0,0: 1(-3.5,1.355) 2(-1,1.355) 3(1,1.355) 4(3.5,1.355)
  round 3.1 hole 2.1: SH1(7,-1.355) SH2(-7,-1.355)
  silkscreen extent -7.22,-11.51 7.22,2.49
USB-C-SMD_TYPEC-304-BCP16#1 [mil]
  oval 39.4x82.7 hole 23.6 slot 70.9 at 90 deg: 13(-170.1,64.3) 14(170.1,64.3)
  oval 39.4x63 hole 23.6 slot 47.2 at 90 deg: 15(-170.1,-100.3) 16(170.1,-100.3)
  rect 23.6x57.1 smd: A1B12(-127,100.3) A4B9(-96.5,100.3) B1A12(126.8,100.3) B4A9(96.5,100.3)
  rect 11.8x57.1 smd: A5(-49.2,100.3) A6(-9.8,100.3) A7(9.8,100.3) A8(49.2,100.3) B5(68.9,100.3) B6(29.5,100.3) B7(-29.5,100.3) B8(-68.9,100.3)
  Board Outline Layer circle w0.2: c117.3,43.4 r13.8
  Board Outline Layer circle w0.2: c-117.3,43.4 r13.8
  Board Outline Layer circle w10: c117.3,43.4 r13.8
  Board Outline Layer circle w10: c-117.3,43.4 r13.8
  Multi-Layer board cut-out: 117.3,29.6 124.11,31.52 129.07,36.56 130.88,43.4 129.07,50.23 124.11,55.27 117.3,57.2 117.3,57.2 110.5,55.28 105.54,50.24 103.72,43.4 105.53,36.56 110.49,31.52 117.3,29.6
  Multi-Layer board cut-out: -117.3,29.6 -110.49,31.52 -105.53,36.56 -103.72,43.4 -105.53,50.23 -110.49,55.27 -117.3,57.2 -117.3,57.2 -124.1,55.28 -129.06,50.24 -130.88,43.4 -129.07,36.56 -124.11,31.52 -117.3,29.6
  silkscreen extent -170,-200 170,120
USB-C-SMD_TYPEC-304-BCP16#2 [mil]
  oval 39.4x82.7 hole 23.6 slot 70.9 at 90 deg: 13(-170.1,64.3) 14(170.1,64.3)
  oval 39.4x63 hole 23.6 slot 47.2 at 90 deg: 15(-170.1,-100.3) 16(170.1,-100.3)
  rect 23.6x57.1 smd: A1B12(-127,100.3) A4B9(-96.5,100.3) B1A12(126.8,100.3) B4A9(96.5,100.3)
  rect 11.8x57.1 smd: A5(-49.2,100.3) A6(-9.8,100.3) A7(9.8,100.3) A8(49.2,100.3) B5(68.9,100.3) B6(29.5,100.3) B7(-29.5,100.3) B8(-68.9,100.3)
  Board Outline Layer circle w0.2: c117.3,43.4 r13.8
  Board Outline Layer circle w0.2: c-117.3,43.4 r13.8
  Board Outline Layer circle w10: c117.3,43.4 r13.8
  Board Outline Layer circle w10: c-117.3,43.4 r13.8
  Multi-Layer board cut-out: 103.5,43.4 105.41,36.58 110.45,31.61 117.3,29.79 124.14,31.61 129.19,36.58 131.1,43.4 131.1,43.4 129.19,50.22 124.14,55.19 117.3,57.01 110.45,55.19 105.41,50.22 103.5,43.4
  Multi-Layer board cut-out: -131.1,43.4 -129.19,36.58 -124.15,31.61 -117.3,29.79 -110.46,31.61 -105.41,36.58 -103.5,43.4 -103.5,43.4 -105.41,50.22 -110.46,55.19 -117.3,57.01 -124.15,55.19 -129.19,50.22 -131.1,43.4
  silkscreen extent -170,-200 170,120

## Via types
v1: diameter 19.7, hole 11.8, Top Layer to Bottom Layer, 425 vias
v2: diameter 19.68, hole 11.81, Top Layer to Bottom Layer, 331 vias
v3: diameter 31.5, hole 19.68, Top Layer to Bottom Layer, 10 vias
v4: diameter 27.56, hole 19.68, Top Layer to Bottom Layer, 2 vias

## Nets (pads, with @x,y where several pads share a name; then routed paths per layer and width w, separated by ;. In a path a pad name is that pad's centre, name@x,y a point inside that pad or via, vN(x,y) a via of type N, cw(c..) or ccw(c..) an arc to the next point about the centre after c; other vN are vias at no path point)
3V3: C13.1 CN4.1 CN7.1 D1.1 D4.1 D5.1 J4.2 J4.4 J8.1 JP3.1 R10.1 R17.1 R26.1 R27.1 R28.1 U8.8 | length 11737.4
  Top Layer w10: R10.1@9075.76,5191.98 9124.16,5191.98 9169.26,5146.98 R17.1@9280.76,5146.98
  Top Layer w15: CN4.1@8933.26,4527.98 8980.46,4480.48 9189.26,4479.18 9257.66,4547.38 9406.16,4547.38 9406.16,4512.98 9406.76,4512.38 U8.8@9406.16,4423.68
  Top Layer w20: v3(8056.02,3482.17) 7999.57,3538.62 7999.57,4945.41 8058.76,5004.61 D5.1@8058.76,5091.44 ; D5.1@8058.76,5107.05 D5.1@8058.76,5091.44 ; D5.1@8078.86,5111.53 D5.1@8058.76,5091.44 ; v3(8524.32,3482.61) 8542.32,3500.61 8542.32,3657.37 8620.57,3735.61 8728.41,3735.61 8794.76,3801.97 v2(8798.21,3801.97) 9432.21,3801.97 9462.21,3831.97 v2(10398.21,3831.97) ; D1.1@9280.21,5373.23 JP3.1@9280.21,5234.97 9280.16,5147.48 R17.1@9280.76,5146.98 ; v4(11854.96,4170.95) 12395.34,4170.95 12606.96,3959.32 13126.05,3959.32 J8.1@13126.44,3959.71
  Bottom Layer w15: v2@9406.76,4512.38 9465.36,4571.08 R28.1@9465.36,4886.28
  Bottom Layer w20: v3(8056.02,3482.17) 8056.47,3482.61 8362.66,3482.61 ; CN7.1@8495.46,3166.58 8495.46,3241.74 D4.1@8449.57,3287.62 8370.57,3366.62 8370.57,3474.71 8362.66,3482.61 ; v3(8524.32,3482.61) 8362.66,3482.61 ; v2@8798.26,3801.98 8798.26,4505.87 ; CN4.1@8933.26,4527.98 8817.56,4528.58 ; JP3.1@9280.21,5234.97 8867.26,5234.98 8798.26,5165.98 8798.26,4547.88 ; v2@10398.26,3831.98 10689.26,3831.98 ; J4.2@10739.86,3565.98 10739.86,3638.78 ; J4.4@10939.86,3565.98 10939.86,3619.38 10902.26,3656.98 10757.56,3656.98 ; v4(11854.96,4170.95) 11515.99,3831.98 10689.26,3831.98 ; 8798.26,4505.87 8817.56,4525.17 8817.56,4528.58 ; 8798.26,4505.87 8798.26,4547.88 ; 8798.26,4547.88 8817.56,4528.58 ; 10689.26,3831.98 10739.86,3781.38 10739.86,3674.68 ; 10739.86,3638.78 10757.56,3656.98 ; 10739.86,3638.78 10739.86,3674.68 ; 10739.86,3674.68 10757.56,3656.98
  other v2: 9406.72,4512.39
5V: CN1.1 CN4.2 CN7.2 D2.1 D3.1 F1.1 J4.5 J7.2 | length 11330.9
  Top Layer w30: v3(8507.66,3316.18) 8479.57,3344.27 8479.57,3658.61 8595.57,3774.61 8713.57,3774.61 8751.21,3812.25 v3(8751.21,3973.97) v3(9078.21,3973.97) ; v3(8752.21,4594.97) 8966.24,4594.97 CN4.2@9033.23,4527.98 ; v3@8776.26,5297.98 F1.1@8776.26,5399.98 ; v3(9155.76,3092.78) v3(12805.2,3092.78) ; v4(12264.57,4411.61) 12340.37,4335.82 D2.1@12880.89,4335.82 ; CN1.1@12929.82,5026.61 CN1.1@12930.72,5027.5
  Bottom Layer w15: v3(10878.79,3093.34) 10879.26,3093.81 10879.26,3404.98 10881.26,3406.98
  Bottom Layer w30: CN7.2@8495.46,3066.58 8547.53,3066.58 8567.57,3086.61 D3.1@8567.57,3315.86 8507.97,3315.86 v3(8507.66,3316.18) ; v3(8751.21,3973.97) 8751.21,5272.97 v3(8776.21,5297.97) ; v3@9078.26,3973.98 9078.26,3170.38 v3(9155.76,3092.78) ; 10881.26,3406.98 J4.5@11039.86,3565.98 ; J7.2@12154.81,4666.56 12264.57,4556.8 v4(12264.57,4411.61) ; v3(12805.2,3092.78) 12915.57,3203.15 v2(12915.57,4233.61) v2(12915.57,4257.61) v2(12915.57,4282.61) 12915.57,4947.75 12930.71,4962.89 CN1.1@12930.72,5027.5
$2N452: C1.2 R1.1 Y1.1 | length 279.2
  Top Layer w6: C1.2@10097.57,4450.17 10097.82,4449.92 Y1.1@10190.1,4449.92 10190.1,4445.99 10231.48,4404.61 10291.04,4404.61 10335.91,4449.48 R1.1@10335.91,4450.61
$2N453: C2.2 R3.1 Y1.3 | length 170
  Top Layer w6: C2.2@10255.13,4282.61 10257.03,4284.52 Y1.3@10257.03,4363.3 10288.26,4363.3 10311.57,4386.61 R3.1@10335.91,4386.61
$2N511: C3.2 R5.1 X1.1 | length 132.1
  Top Layer w5.98: X1.1@10374.96,4795.3 10404.05,4795.3 10413.42,4804.66 R5.1@10440.15,4804.66
  Bottom Layer w5.98: C3.2@10316.17,4805.53 10339.88,4805.53 10350.12,4795.3 X1.1@10374.96,4795.3
$2N512: C4.2 R6.1 X1.2 | length 129.8
  Top Layer w5.98: X1.2@10374.97,4755.93 10402.38,4755.93 10410.38,4747.93 R6.1@10440.15,4747.93
  Bottom Layer w5.98: C4.2@10316.17,4749.97 10346.4,4749.97 10352.35,4755.93 X1.2@10374.97,4755.93
$2N701: JP1.2 R13.1 | length 455.4
  Bottom Layer w6: JP1.2@8926.26,4889.98 8887.16,4889.98 8850.26,4852.98 8850.26,4674.98 8897.16,4627.98 R13.1@9016.76,4627.98
$2N702: JP2.2 R14.1 | length 244.9
  Bottom Layer w6: R14.1@9017.76,4683.98 9011.76,4683.98 8984.26,4711.48 8984.26,4837.98 JP2.2@9036.26,4889.98
$3N58: C5.1 C6.1 F1.2 U2.1 U2.3 | length 369.5
  Top Layer w6: U2.1@8971.16,5465.98 9014.56,5464.58 9026.26,5452.98 9026.26,5402.98 9014.16,5390.98 U2.3@8984.26,5390.98
  Top Layer w30: F1.2@8776.26,5459.28 8778.36,5457.08 8836.21,5457.08 8891.21,5457.08 8917.86,5457.08 8926.66,5465.98 8971.16,5465.98 U2.1@8984.26,5465.98
$3N81: R15.1 R16.1 U2.4 | length 160.8
  Top Layer w20: U2.4@9084.26,5390.98 9111.16,5390.98 9130.76,5410.48 9150.26,5410.48 9150.26,5324.48 R15.1@9149.66,5323.98
$3N82: C7.1 D1.2 R16.2 U2.5 | length 196.6
  Top Layer w20: U2.5@9084.26,5465.98 9114.76,5465.98 9115.16,5465.48 9150.16,5465.48 9151.46,5466.68 D1.2@9280.21,5466.73
$3N119: LED1.1 R10.2 | length 64.5
  Top Layer w10: LED1.1@8956.26,5192.78 R10.2@9020.76,5191.98
$3N184: B2.2 B2.4 R18.2 R19.1 R20.1 | length 568
  Top Layer w6: B2.4@8828.03,3521.56 B2.2@9174.49,3521.56 9252.26,3521.58 9278.66,3547.98 9277.66,3548.98 R19.1@9277.66,3653.98
$3N504: LED2.1 R26.2 | length 104.4
  Top Layer w10: v2@9358.66,4734.58 9359.26,4735.18 LED2.1@9411.01,4735.2
  Bottom Layer w10: v2@9358.66,4734.58 9359.06,4734.98 R26.2@9410.36,4734.98
  other v2: 9358.65,4734.61
$3N505: LED3.1 R27.2 | length 104.1
  Top Layer w10: v2@9358.66,4809.98 LED3.1@9411.06,4810.18
  Bottom Layer w10: v2@9358.66,4809.98 R27.2@9410.36,4809.98
  other v2: 9358.65,4810
$3N506: LED4.1 R28.2 | length 104.1
  Top Layer w10: v2@9358.66,4886.28 LED4.1@9411.06,4886.48
  Bottom Layer w10: v2@9358.66,4886.28 R28.2@9410.36,4886.28
  other v2: 9358.65,4886.3
$3N17443: CN2.B5 R33.2 | length 202.1
  Top Layer w6: R33.2@12941.23,4508.61 13010.57,4508.61 13064.67,4562.72 CN2.B5@13120.94,4562.72
$3N17484: CN2.A5 R32.2 | length 177.7
  Top Layer w5.98: R32.2@12943.23,4444.61 CN2.A5@13120.94,4444.62
$3N17593: JP4.2 R34.1 | length 131.8
  Top Layer w6: JP4.2@12795.57,4668.61 12881.91,4582.27 R34.1@12881.91,4572.61
$4N269: J6.5 R56.2 R57.2 | length 163
  Bottom Layer w6: R56.2@11886.26,3678.68 11892.46,3672.48 11940.16,3672.48 J6.5@11939.86,3565.98
$4N270: J6.6 R58.2 R59.2 | length 168.5
  Bottom Layer w6: J6.6@12039.8,3565.97 12039.81,3667.56 R59.2@12037.06,3670.3 12089.36,3670.3 R58.2@12096.95,3677.89
$4N339: J3.3 R60.1 R61.2 | length 161.8
  Bottom Layer w6: R60.1@10926.16,5357.28 10926.16,5362.48 10979.26,5362.48 J3.3@10979.86,5465.98
$6N792: LD1.1 RP1.8 | length 121.7
  Top Layer w6: RP1.8@8360.2,4965.45 8363.16,4965.45 8397.25,4999.55 8397.25,5009.62 8439.43,5051.8 LD1.1@8439.43,5052.63
$6N793: LD2.1 RP1.7 | length 98.6
  Top Layer w6: RP1.7@8360.2,4933.96 8393.82,4933.96 8438.39,4978.53 LD2.1@8440.39,4978.53
$6N794: LD3.1 RP1.6 | length 80.6
  Top Layer w6: RP1.6@8360.2,4902.46 8415.6,4902.46 8416.43,4901.63 LD3.1@8440.43,4901.63
$6N795: LD4.1 RP1.5 | length 99
  Top Layer w6: RP1.5@8360.2,4870.97 8393.05,4870.97 8438.39,4825.63 LD4.1@8440.39,4825.63
$6N16959: C15.2 C16.2 C18.2 C19.2 F2.2 U5.1 U5.3 U7.1 U7.3 | length 955.4
  Top Layer w6: v2(8079.97,5471.01) 8079.97,5424.64 U5.3@8080.56,5424.05 ; U7.3@8449.34,5418.39 8449.34,5386.85 8465.17,5371.01 8510.77,5371.01 8524.34,5384.58 U7.1@8524.34,5418.39
  Top Layer w15: v2(8079.97,5471.01) 8079.97,5504.25 8077.97,5506.25 8149.57,5506.25 C19.2@8150.37,5505.45 8155.56,5500.26 U5.1@8155.56,5424.05 ; v2(8376.76,5469.02) 8376.76,5500.59 F2.2@8377.56,5501.39 ; C16.2@8517.56,5506.49 8517.56,5471.42 8524.34,5464.65 U7.1@8524.34,5418.39
  Top Layer w20: F2.2@8377.56,5501.39 8512.46,5501.39 C16.2@8517.56,5506.49
  Bottom Layer w15: v2(8079.97,5471.01) 8081.17,5469.81 8375.97,5469.81 v2(8376.76,5469.02)
$6N17598: R43.2 R49.1 U7.4 | length 144.7
  Top Layer w6: R49.1@8387.57,5252.95 8439.57,5252.95 8440.03,5253.41 R43.2@8461.9,5253.41 8461.9,5290.28 8449.34,5302.85 U7.4@8449.34,5318.39
$6N17675: R50.2 R51.1 U5.4 | length 146.5
  Top Layer w6: R51.1@8029.57,5238.95 8052.89,5238.95 8064.98,5251.05 R50.2@8092.9,5251.05 8092.9,5275.68 8080.56,5288.02 U5.4@8080.56,5324.05
ATLINK_5V: CN6.A4B9 CN6.B4A9 D3.2 F2.1 TP3.1 | length 3362.8
  Top Layer w20: CN6.B4A9@8200.71,5717.9 8200.71,5609.88 8201.17,5609.41 ; v2(8362.76,5609.37) 8362.76,5575.52 F2.1@8377.56,5560.71 ; CN6.A4B9@8393.71,5717.9 8394.27,5717.34 v2(8394.27,5611.13)
  Bottom Layer w15: v2(8394.27,5611.13) 8414.58,5590.82 TP3.1@8414.58,5526.61
  Bottom Layer w30: v2(8394.27,5611.13) 8392.51,5609.37 v2(8362.76,5609.37) 8361.51,5610.61 v2(8213.24,5610.61) v2(8186.47,5610.61) 8083.57,5610.61 8042.25,5569.3 8042.25,3597.93 8108.3,3531.88 8537.57,3531.88 8567.57,3501.88 D3.2@8567.57,3409.36
ATLK_BOOT0: R45.1 U6.27 | length 395.7
  Top Layer w6: U6.27@8203.01,4337.98 8202.96,3998.78 8218.46,3983.38 R45.1@8218.46,3948.68
ATLK_NRST: R46.1 U6.28 | length 419.2
  Top Layer w6: U6.28@8222.69,4337.98 8222.66,4049.48 8292.46,3979.78 R46.1@8292.46,3947.68
ATLK_RX: CN4.10 CN7.10 R25.1 R48.2 | length 2281.5
  Top Layer w6: v2(8219.86,3386.38) 8219.86,3578.78 v2(8220.26,3579.18) ; v2@8425.16,3576.68 v2(8422.66,3579.18) 8422.66,3788.08 8443.66,3809.08 R48.2@8443.66,3892.68
  Bottom Layer w6: CN7.10@8095.46,3066.58 8145.96,3117.18 8145.96,3312.48 v2(8219.86,3386.38) ; v2(8220.26,3579.18) v2(8422.66,3579.18) 8545,3579.18 8579.46,3544.73 8913.43,3544.73 9007.59,3638.89 9007.59,4102.34 CN4.10@9033.23,4127.98 ; CN4.10@9061.16,4128.18 9066.16,4123.08 R25.1@9110.16,4123.08
ATLK_SWCLK: R41.1 U6.25 | length 427
  Top Layer w6: R41.1@8070.46,3949.58 8070.46,3979.08 8163.66,4072.28 U6.25@8163.66,4337.98
ATLK_SWDIO: R44.1 U6.26 | length 404.5
  Top Layer w6: R44.1@8144.46,3949.58 8144.46,3993.08 8183.36,4031.98 U6.26@8183.36,4337.98
ATLK_SWO: R52.1 U6.13 | length 530.4
  Top Layer w6: R52.1@8070.26,4142.58 8070.26,4218.73 8042.65,4246.34 8042.65,4589.69 8066.53,4613.58 U6.13@8104.58,4613.57
ATLK_TX: CN4.8 CN7.8 R24.1 R47.2 | length 2247.2
  Top Layer w6: v2(8302.46,3348.18) 8367.5,3413.22 v2(8367.5,3603.41) 8367.5,3846.62 8367.66,3846.78 R47.2@8367.66,3892.68
  Bottom Layer w6: CN7.8@8195.43,3066.63 8244,3115.2 8244,3289.72 v2(8302.46,3348.18) ; v2(8367.5,3603.41) 8368.11,3604.03 8550.15,3604.03 8592.12,3562.06 8900.43,3562.06 8985.14,3646.77 8985.14,4179.88 CN4.8@9033.23,4227.98 ; CN4.8@9033.26,4227.98 9078.86,4227.98 9080.96,4229.98 R24.1@9110.76,4229.98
